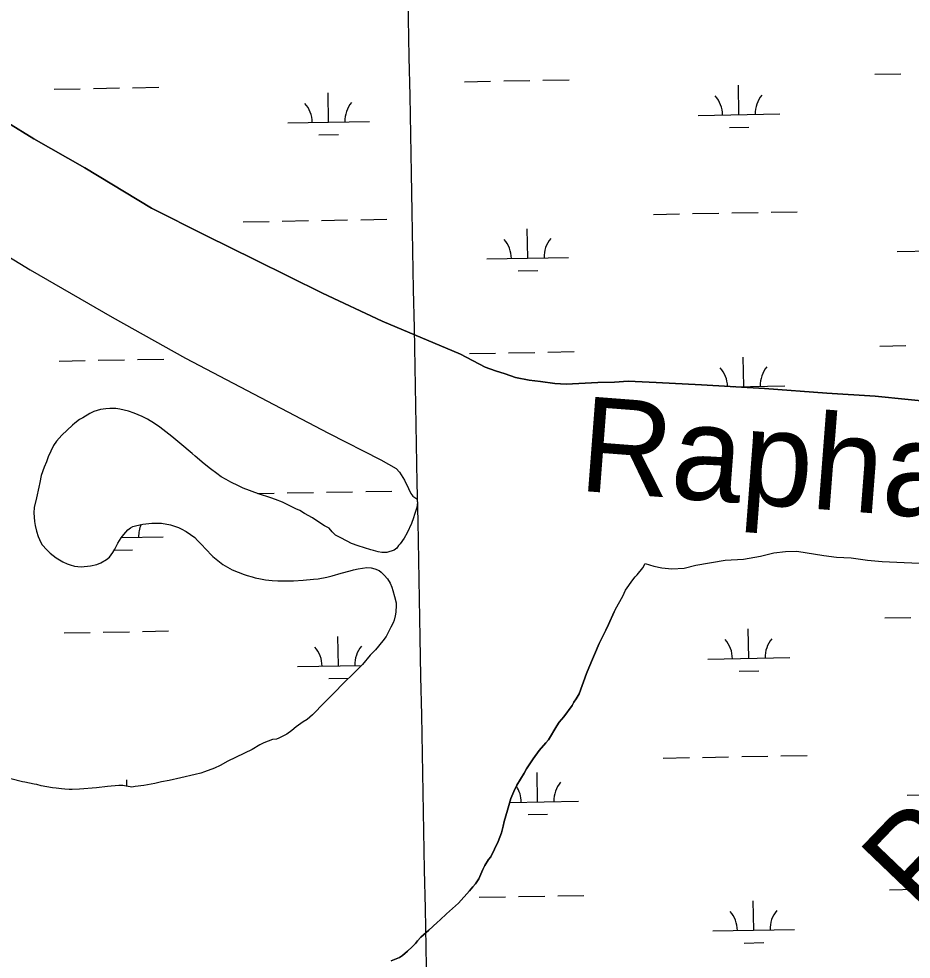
# Model space of a CAD drawing. Extents: x 3957609 to 3995875, y 234277 to 260273.
# Drawn here: x 3971801 to 3972892, y 251198 to 252348 of the extents above; entities that cross this region are included whole.
import ezdxf

# ---------------------------------------------------------------- set-up
doc = ezdxf.new("R2010")
doc.units = 0
for name, color, linetype in [('V-GRID-MAJR', 7, 'Continuous'), ('V-RIVR-IDEN', 7, 'Continuous'), ('V-TOPO-SHOR', 7, 'Continuous'), ('V-WETL-SWMP', 7, 'Continuous')]:
    doc.layers.add(name, color=color, linetype=linetype)

msp = doc.modelspace()

# ---------------------------------------------------------------- linework, layer by layer
at = {"layer": 'V-GRID-MAJR'}
msp.add_spline([(3972513.068, 239900.828), (3972455.83, 242927.648), (3972341.236, 248987.469), (3972226.642, 255047.279), (3972169.287, 258080.274)], degree=3, dxfattribs=at)
at = {"layer": 'V-TOPO-SHOR'}
for points in [[(3971429.884, 252268.018), (3971443.683, 252260.164), (3971459.059, 252249.556), (3971499.661, 252228.746), (3971570.618, 252189.474), (3971649.861, 252141.55), (3971729.498, 252093.629), (3971815.051, 252041.385), (3971915.184, 251983.254), (3972005.064, 251933.379), (3972179.691, 251841.498), (3972243.943, 251808.91), (3972262.471, 251798.308), (3972266.418, 251793.587), (3972272.736, 251784.144), (3972277.477, 251773.912), (3972280.639, 251767.614), (3972283.007, 251764.468), (3972287.74, 251760.932)], [(3971753.003, 252242.246), (3971819.63, 252201.786), (3971881.916, 252166.046), (3971963.525, 252116.946), (3972029.749, 252083.18), (3972090.054, 252053.738), (3972172.437, 252012.909), (3972245.356, 251978.37), (3972341.129, 251937.957), (3972371.48, 251922.25), (3972384.092, 251917.544), (3972395.915, 251914.02), (3972408.524, 251909.706), (3972425.072, 251906.188), (3972438.859, 251904.636), (3972456.587, 251902.301), (3972470.372, 251901.535), (3972508.969, 251903.567), (3972529.449, 251903.995), (3972546.381, 251905.203), (3972580.651, 251903.288), (3972635.795, 251900.622), (3972712.999, 251896.02), (3972789.416, 251890.234), (3972848.5, 251886.785), (3972928.86, 251878.642)], [(3972287.74, 251760.932), (3972288.46, 251756.467), (3972287.756, 251750.569), (3972286.691, 251746.817), (3972284.911, 251741.99), (3972283.846, 251737.879), (3972281.356, 251731.086), (3972275.837, 251719.466), (3972272.273, 251712.849), (3972267.46, 251706.232), (3972265.5, 251703.905), (3972263.36, 251700.686), (3972260.149, 251698.181), (3972251.222, 251695.664), (3972245.147, 251695.656), (3972240.679, 251696.362), (3972234.78, 251697.781), (3972231.743, 251698.67), (3972216.193, 251703.647), (3972207.792, 251706.672), (3972202.426, 251709.162), (3972194.023, 251713.617), (3972188.479, 251716.824), (3972184.365, 251720.926), (3972180.785, 251725.386), (3972174.706, 251728.055), (3972162.902, 251735.897), (3972160.041, 251738.037), (3972150.562, 251743.202), (3972144.662, 251746.766), (3972139.835, 251748.902), (3972128.393, 251754.779), (3972123.386, 251757.094), (3972115.163, 251760.295), (3972109.265, 251762.431), (3972094.07, 251767.407), (3972075.481, 251774.346), (3972069.58, 251776.836), (3972060.463, 251781.467), (3972054.56, 251784.674), (3972048.482, 251788.235), (3972043.114, 251791.979), (3972035.424, 251797.685), (3972027.912, 251803.745), (3972016.82, 251813.197), (3972012.884, 251816.762), (3971997.857, 251829.245), (3971988.375, 251837.447), (3971973.707, 251848.678), (3971967.088, 251853.491), (3971958.505, 251858.48), (3971952.068, 251861.863), (3971942.058, 251866.135), (3971935.264, 251868.447), (3971924.721, 251870.932), (3971919.896, 251871.816), (3971912.392, 251871.804), (3971907.569, 251871.44), (3971900.96, 251870.534), (3971892.926, 251868.021), (3971887.749, 251865.691), (3971879.36, 251860.139), (3971875.256, 251857.988), (3971869.724, 251853.87), (3971866.691, 251851.363), (3971853.848, 251839.196), (3971847.071, 251831.86), (3971843.328, 251826.494), (3971837.098, 251812.549), (3971834.785, 251806.293), (3971832.117, 251799.678), (3971828.56, 251789.847), (3971826.608, 251780.912), (3971825.723, 251775.55), (3971822.706, 251762.504), (3971819.69, 251750.708), (3971819.344, 251744.097), (3971820.253, 251733.38), (3971821.154, 251728.557), (3971822.774, 251721.594), (3971824.748, 251715.165), (3971828.154, 251707.845), (3971829.768, 251704.81), (3971835.316, 251698.568), (3971839.252, 251694.82), (3971846.764, 251689.116), (3971854.813, 251684.127), (3971860.177, 251681.635), (3971863.931, 251680.212), (3971869.292, 251678.79), (3971873.044, 251678.262), (3971877.333, 251677.912), (3971888.584, 251679.179), (3971896.443, 251680.98), (3971901.442, 251682.952), (3971908.225, 251686.892), (3971911.792, 251689.936), (3971916.071, 251695.482), (3971918.565, 251699.594), (3971922.307, 251706.746), (3971926.405, 251713.543)], [(3971926.405, 251713.543), (3971929.434, 251717.655), (3971934.249, 251723.023), (3971937.462, 251725.708), (3971940.673, 251727.142), (3971943.71, 251728.041), (3971952.64, 251730.199), (3971963.891, 251731.289), (3971970.68, 251731.477), (3971975.504, 251731.307), (3971986.763, 251729.181), (3971992.483, 251727.404), (3971996.237, 251725.98), (3971999.811, 251724.379), (3972005.714, 251721.352), (3972016.265, 251713.686), (3972019.665, 251710.119), (3972025.391, 251704.589), (3972029.151, 251700.309), (3972038.455, 251690.677), (3972050.442, 251680.691), (3972062.064, 251674.1), (3972076.722, 251668.585), (3972080.476, 251667.52), (3972086.374, 251665.564), (3972090.306, 251664.497), (3972096.561, 251663.078), (3972102.637, 251662.017), (3972111.034, 251661.137), (3972118.003, 251660.791), (3972122.468, 251660.977), (3972128.901, 251660.987), (3972136.939, 251660.821), (3972148.73, 251661.554), (3972161.591, 251662.648), (3972167.307, 251663.371), (3972177.666, 251665.353), (3972184.451, 251666.973), (3972195.166, 251670.205), (3972206.237, 251672.902), (3972210.165, 251674.16), (3972215.879, 251675.6), (3972226.597, 251677.224), (3972232.134, 251676.875), (3972236.603, 251675.632), (3972241.789, 251673.496), (3972244.293, 251671.356), (3972247.871, 251667.789), (3972251.809, 251663.152), (3972255.033, 251657.975), (3972257.185, 251652.975), (3972258.443, 251648.869), (3972260.597, 251641.728), (3972262.398, 251633.87), (3972262.58, 251630.832), (3972262.058, 251622.614), (3972261.351, 251617.789), (3972260.11, 251612.605), (3972258.685, 251609.21), (3972256.192, 251604.024), (3972250.493, 251592.76), (3972246.392, 251587.214), (3972237.299, 251576.483), (3972230.879, 251569.683), (3972221.427, 251558.591), (3972211.439, 251548.749), (3972207.337, 251544.456), (3972201.451, 251538.908), (3972183.259, 251520.654), (3972177.729, 251514.752), (3972169.169, 251506.341), (3972165.779, 251502.583), (3972160.252, 251496.858), (3972153.649, 251491.308), (3972148.652, 251488.085), (3972140.087, 251482.176), (3972135.092, 251477.88), (3972128.667, 251473.224), (3972119.208, 251468.207), (3972116.172, 251466.951), (3972111.349, 251466.587), (3972100.815, 251462.46), (3972095.996, 251460.13), (3972086.536, 251454.577), (3972056.723, 251440.237), (3972047.263, 251435.042), (3972040.302, 251431.636), (3972027.984, 251426.97), (3972023.519, 251425.535), (3972016.734, 251423.737), (3971999.053, 251419.956), (3971984.767, 251416.36), (3971975.657, 251414.738), (3971970.836, 251413.478), (3971967.264, 251412.937), (3971953.868, 251410.414), (3971943.331, 251408.968), (3971939.401, 251408.248), (3971928.144, 251410.195), (3971923.32, 251410.187), (3971909.388, 251409.272)], [(3972567.111, 251681.821), (3972577.751, 251678.688), (3972587.602, 251676.734), (3972599.814, 251675.573), (3972614.779, 251676.386), (3972628.951, 251679.952), (3972664.783, 251685.917), (3972687.231, 251687.136), (3972708.1, 251691.107), (3972724.24, 251695.072), (3972738.812, 251696.671), (3972752.595, 251697.087), (3972785.688, 251691.627), (3972801.052, 251689.682), (3972818.778, 251688.924), (3972838.869, 251686.198), (3972856.987, 251684.259), (3972920.01, 251681.602)], [(3972530.854, 251626.128), (3972539.58, 251641.865), (3972543.142, 251649.373), (3972551.876, 251662.071), (3972554.727, 251665.648), (3972557.226, 251668.153), (3972564.359, 251676.74), (3972567.111, 251681.821)], [(3972530.854, 251626.128), (3972529.072, 251622.73), (3972522.129, 251607.178), (3972518.746, 251600.561), (3972516.61, 251595.734), (3972510.912, 251583.933), (3972498.098, 251554.258), (3972495.249, 251547.286), (3972486.537, 251522.618), (3972482.793, 251516.538), (3972479.942, 251512.245), (3972477.804, 251508.311), (3972467.466, 251494.54), (3972461.938, 251487.921), (3972458.907, 251483.448), (3972448.751, 251466.46), (3972445.72, 251462.526), (3972437.34, 251453.043), (3972430.031, 251443.205), (3972427.714, 251439.271), (3972421.832, 251430.687), (3972418.984, 251425.502), (3972410.253, 251410.658), (3972406.335, 251402.972), (3972402.956, 251394.391), (3972398.512, 251380.27), (3972394.782, 251366.151), (3972393.541, 251360.609), (3972391.231, 251352.567), (3972387.139, 251342.019), (3972378.417, 251323.069), (3972375.564, 251319.848), (3972371.107, 251312.694), (3972368.615, 251307.689), (3972363.452, 251296.068), (3972359.532, 251289.988), (3972356.501, 251286.588), (3972352.221, 251281.401), (3972338.667, 251266.551), (3972324.219, 251253.306), (3972316.549, 251245.97), (3972312.803, 251242.927), (3972302.454, 251233.443), (3972295.854, 251227.714), (3972292.823, 251224.851), (3972288.721, 251220.378), (3972286.224, 251217.159), (3972282.3, 251212.864), (3972276.592, 251207.496), (3972270.348, 251202.483), (3972266.6, 251199.798), (3972256.602, 251195.851)], [(3971909.388, 251409.272), (3971895.992, 251407.641), (3971875.448, 251405.823), (3971866.339, 251405.628), (3971862.765, 251405.622), (3971857.406, 251405.972), (3971853.295, 251406.322), (3971846.684, 251407.205), (3971842.396, 251407.555), (3971828.279, 251410.033), (3971822.915, 251411.455), (3971819.7, 251411.985), (3971808.442, 251414.467), (3971805.403, 251415), (3971775.021, 251422.633)]]:
    msp.add_lwpolyline(points, dxfattribs=at)
at = {"layer": 'V-WETL-SWMP'}
for p, q in [((3972346.071, 252271.505), (3972378.065, 252272.087)), ((3972394.063, 252272.378), (3972426.058, 252272.96)), ((3972442.055, 252273.251), (3972474.05, 252273.832)), ((3972847.896, 252280.63), (3972879.89, 252281.212)), ((3971844.246, 252262.381), (3971876.24, 252262.962)), ((3971892.238, 252263.253), (3971924.232, 252263.835)), ((3971940.23, 252264.126), (3971972.225, 252264.708)), ((3972681.703, 252231.17), (3972681.049, 252267.164)), ((3972179.878, 252222.046), (3972179.224, 252258.04)), ((3972631.712, 252230.261), (3972731.695, 252232.079)), ((3972129.887, 252221.137), (3972229.87, 252222.955)), ((3972669.986, 252215.524), (3972693.982, 252215.96)), ((3972168.161, 252206.399), (3972192.157, 252206.835)), ((3972625.052, 252110.049), (3972657.047, 252110.631)), ((3972673.044, 252110.922), (3972705.039, 252111.504)), ((3972721.036, 252111.795), (3972753.031, 252112.377)), ((3972075.235, 252100.052), (3972107.23, 252100.634)), ((3972123.227, 252100.925), (3972155.222, 252101.506)), ((3972171.219, 252101.797), (3972203.214, 252102.379)), ((3972219.211, 252102.67), (3972251.206, 252103.252)), ((3972577.06, 252109.177), (3972609.055, 252109.759)), ((3972423.416, 252055.633), (3972422.762, 252091.627)), ((3972875.249, 252063.848), (3972975.233, 252065.666)), ((3972373.424, 252054.724), (3972473.408, 252056.542)), ((3972411.699, 252039.986), (3972435.695, 252040.422)), ((3972352.119, 251938.885), (3972384.113, 251939.467)), ((3972400.111, 251939.758), (3972432.106, 251940.34)), ((3972448.103, 251940.631), (3972480.098, 251941.212)), ((3972853.944, 251948.01), (3972885.939, 251948.592)), ((3971850.294, 251929.76), (3971882.288, 251930.342)), ((3971898.286, 251930.633), (3971930.281, 251931.215)), ((3971946.278, 251931.506), (3971978.273, 251932.088)), ((3972687.752, 251898.55), (3972687.097, 251934.544)), ((3972674.557, 251898.31), (3972737.743, 251899.459)), ((3972093.413, 251767.653), (3972113.278, 251768.014)), ((3972129.275, 251768.305), (3972161.27, 251768.886)), ((3972177.267, 251769.177), (3972209.262, 251769.759)), ((3972225.259, 251770.05), (3972257.254, 251770.632)), ((3971926.645, 251713.87), (3971977.631, 251714.797)), ((3971927.639, 251713.888), (3971927.615, 251715.187)), ((3971917.766, 251698.275), (3971939.918, 251698.678)), ((3972859.992, 251615.39), (3972891.987, 251615.972)), ((3971856.342, 251597.14), (3971888.336, 251597.722)), ((3971904.334, 251598.013), (3971936.329, 251598.595)), ((3971952.326, 251598.886), (3971984.321, 251599.468)), ((3972191.975, 251556.806), (3972191.32, 251592.8)), ((3972693.8, 251565.93), (3972693.145, 251601.924)), ((3972643.808, 251565.021), (3972743.791, 251566.839)), ((3972141.983, 251555.897), (3972220.136, 251557.318)), ((3972682.082, 251550.284), (3972706.078, 251550.72)), ((3972180.257, 251541.159), (3972204.253, 251541.595)), ((3972589.156, 251443.937), (3972621.151, 251444.519)), ((3972637.148, 251444.809), (3972669.143, 251445.391)), ((3972685.14, 251445.682), (3972717.135, 251446.264)), ((3972733.132, 251446.555), (3972765.127, 251447.136)), ((3972435.512, 251390.393), (3972434.858, 251426.387)), ((3971933.177, 251409.325), (3971933.033, 251417.262)), ((3972887.346, 251398.608), (3972987.329, 251400.426)), ((3972401.502, 251389.774), (3972485.504, 251391.302)), ((3972423.795, 251374.746), (3972447.791, 251375.182)), ((3972866.04, 251282.77), (3972898.035, 251283.352)), ((3972364.215, 251273.645), (3972396.21, 251274.227)), ((3972412.207, 251274.518), (3972444.202, 251275.1)), ((3972460.199, 251275.39), (3972492.194, 251275.972)), ((3972699.848, 251233.31), (3972699.193, 251269.304)), ((3972649.856, 251232.401), (3972749.839, 251234.219)), ((3972688.13, 251217.664), (3972712.126, 251218.1))]:
    msp.add_line(p, q, dxfattribs=at)
for points in [[(3972928.86, 251878.643), (3972848.5, 251886.785), (3972789.416, 251890.234), (3972712.998, 251896.019), (3972635.795, 251900.621), (3972580.65, 251903.289), (3972546.382, 251905.203), (3972529.448, 251903.994), (3972508.968, 251903.567), (3972470.373, 251901.535), (3972456.587, 251902.301), (3972438.859, 251904.635), (3972425.072, 251906.189), (3972408.524, 251909.707), (3972395.914, 251914.019), (3972384.092, 251917.544), (3972371.481, 251922.25), (3972341.129, 251937.956), (3972245.357, 251978.369), (3972172.437, 252012.91), (3972090.055, 252053.739), (3972029.748, 252083.181), (3971963.525, 252116.946), (3971881.917, 252166.046), (3971819.63, 252201.787), (3971753.003, 252242.247)], [(3971729.498, 252093.629), (3971815.05, 252041.384), (3971915.184, 251983.254), (3972005.064, 251933.379), (3972179.692, 251841.497), (3972243.943, 251808.911), (3972262.472, 251798.307), (3972266.418, 251793.587), (3972272.735, 251784.144), (3972277.478, 251773.911), (3972280.639, 251767.615), (3972283.007, 251764.468), (3972287.739, 251760.931), (3972288.461, 251756.466), (3972287.756, 251750.569), (3972286.69, 251746.816), (3972284.911, 251741.989), (3972283.846, 251737.879), (3972281.356, 251731.086), (3972275.836, 251719.465), (3972272.274, 251712.849), (3972267.461, 251706.231), (3972265.5, 251703.905), (3972263.361, 251700.686), (3972260.149, 251698.18), (3972251.221, 251695.664), (3972245.147, 251695.655), (3972240.679, 251696.362), (3972234.781, 251697.782), (3972231.743, 251698.67), (3972216.192, 251703.647), (3972207.791, 251706.671), (3972202.427, 251709.163), (3972194.023, 251713.616), (3972188.48, 251716.823), (3972184.364, 251720.925), (3972180.784, 251725.386), (3972174.706, 251728.056), (3972162.902, 251735.897), (3972160.04, 251738.036), (3972150.563, 251743.202), (3972144.662, 251746.765), (3972139.835, 251748.902), (3972128.392, 251754.779), (3972123.386, 251757.093), (3972115.163, 251760.295), (3972109.264, 251762.43), (3972094.071, 251767.407), (3972075.48, 251774.345), (3972069.58, 251776.836), (3972060.462, 251781.467), (3972054.561, 251784.673), (3972048.481, 251788.236), (3972043.115, 251791.979), (3972035.424, 251797.684), (3972027.911, 251803.746), (3972016.82, 251813.196), (3972012.883, 251816.763), (3971997.857, 251829.244), (3971988.375, 251837.447), (3971973.707, 251848.678), (3971967.089, 251853.491), (3971958.506, 251858.48), (3971952.069, 251861.864), (3971942.058, 251866.135), (3971935.265, 251868.447), (3971924.721, 251870.931), (3971919.896, 251871.816), (3971912.393, 251871.804), (3971907.57, 251871.439), (3971900.961, 251870.535), (3971892.926, 251868.021), (3971887.749, 251865.69), (3971879.361, 251860.139), (3971875.256, 251857.988), (3971869.724, 251853.87), (3971866.691, 251851.364), (3971853.848, 251839.195), (3971847.071, 251831.86), (3971843.328, 251826.494), (3971837.097, 251812.549), (3971834.785, 251806.293), (3971832.116, 251799.678), (3971828.559, 251789.847), (3971826.608, 251780.911), (3971825.723, 251775.55), (3971822.707, 251762.504), (3971819.689, 251750.708), (3971819.343, 251744.097), (3971820.253, 251733.379), (3971821.154, 251728.557), (3971822.773, 251721.593), (3971824.749, 251715.164), (3971828.155, 251707.845), (3971829.768, 251704.811)], [(3971829.768, 251704.811), (3971835.316, 251698.567), (3971839.252, 251694.821), (3971846.765, 251689.117), (3971854.812, 251684.127), (3971860.176, 251681.635), (3971863.93, 251680.212), (3971869.292, 251678.791), (3971873.044, 251678.261), (3971877.332, 251677.911), (3971888.585, 251679.18), (3971896.443, 251680.979), (3971901.442, 251682.952), (3971908.225, 251686.893), (3971911.793, 251689.936), (3971916.071, 251695.481), (3971918.566, 251699.594), (3971922.306, 251706.746), (3971926.404, 251713.542), (3971929.434, 251717.656), (3971934.249, 251723.023), (3971937.461, 251725.708), (3971940.674, 251727.142), (3971943.71, 251728.04), (3971952.639, 251730.199), (3971963.892, 251731.289), (3971970.681, 251731.478), (3971975.504, 251731.307), (3971986.763, 251729.182), (3971992.483, 251727.404), (3971996.237, 251725.981), (3971999.812, 251724.379), (3972005.713, 251721.352), (3972016.265, 251713.687), (3972019.665, 251710.119), (3972025.391, 251704.59), (3972029.15, 251700.309), (3972038.455, 251690.676), (3972050.441, 251680.691), (3972062.064, 251674.1), (3972076.722, 251668.585), (3972080.476, 251667.52), (3972086.374, 251665.564), (3972090.306, 251664.498), (3972096.561, 251663.079), (3972102.637, 251662.017), (3972111.035, 251661.137), (3972118.003, 251660.791), (3972122.469, 251660.977), (3972128.901, 251660.988), (3972136.94, 251660.822), (3972148.73, 251661.555), (3972161.591, 251662.648), (3972167.307, 251663.372), (3972177.665, 251665.354), (3972184.451, 251666.973), (3972195.165, 251670.206), (3972206.237, 251672.903), (3972210.166, 251674.16), (3972215.88, 251675.599), (3972226.597, 251677.224), (3972232.135, 251676.875), (3972236.604, 251675.632), (3972241.788, 251673.496), (3972244.293, 251671.357), (3972247.871, 251667.789), (3972251.809, 251663.151), (3972255.033, 251657.975), (3972257.185, 251652.976), (3972258.442, 251648.869), (3972260.598, 251641.727), (3972262.397, 251633.869), (3972262.58, 251630.832), (3972262.058, 251622.614), (3972261.351, 251617.789), (3972260.109, 251612.606), (3972258.685, 251609.209), (3972256.192, 251604.024), (3972250.493, 251592.76), (3972246.393, 251587.215), (3972237.299, 251576.482), (3972230.879, 251569.683), (3972221.428, 251558.591), (3972211.44, 251548.749), (3972207.338, 251544.455), (3972201.451, 251538.907), (3972183.258, 251520.655), (3972177.73, 251514.751), (3972169.168, 251506.34), (3972165.78, 251502.583), (3972160.251, 251496.858), (3972153.649, 251491.309), (3972148.652, 251488.085), (3972140.087, 251482.176), (3972135.091, 251477.88), (3972128.667, 251473.225), (3972119.207, 251468.207), (3972116.172, 251466.952), (3972111.349, 251466.587), (3972100.815, 251462.461), (3972095.995, 251460.13)], [(3972599.813, 251675.573), (3972614.778, 251676.385), (3972628.951, 251679.952), (3972664.783, 251685.918), (3972687.231, 251687.136), (3972708.099, 251691.108), (3972724.241, 251695.072), (3972738.811, 251696.671), (3972752.595, 251697.087), (3972785.688, 251691.627), (3972801.052, 251689.682), (3972818.777, 251688.923), (3972838.868, 251686.198), (3972856.988, 251684.258), (3972920.01, 251681.603)], [(3972256.602, 251195.851), (3972266.6, 251199.798), (3972270.348, 251202.483), (3972276.593, 251207.496), (3972282.301, 251212.864), (3972286.224, 251217.158), (3972288.72, 251220.378), (3972292.822, 251224.851), (3972295.854, 251227.714), (3972302.455, 251233.442), (3972312.802, 251242.927), (3972316.548, 251245.97), (3972324.219, 251253.307), (3972338.668, 251266.551), (3972352.221, 251281.401), (3972356.501, 251286.588), (3972359.532, 251289.988), (3972363.453, 251296.068), (3972368.615, 251307.689), (3972371.108, 251312.695), (3972375.563, 251319.848), (3972378.416, 251323.069), (3972387.139, 251342.02), (3972391.231, 251352.567), (3972393.541, 251360.61), (3972394.782, 251366.15), (3972398.511, 251380.269), (3972402.955, 251394.39), (3972406.335, 251402.971), (3972410.253, 251410.659), (3972418.983, 251425.501), (3972421.833, 251430.687), (3972427.715, 251439.271), (3972430.031, 251443.205), (3972437.34, 251453.043), (3972445.721, 251462.525), (3972448.752, 251466.46), (3972458.908, 251483.448), (3972461.938, 251487.92), (3972467.465, 251494.539), (3972477.805, 251508.311), (3972479.942, 251512.245), (3972482.794, 251516.537), (3972486.536, 251522.618), (3972495.25, 251547.286), (3972498.097, 251554.258), (3972510.912, 251583.934), (3972516.61, 251595.734), (3972518.746, 251600.561), (3972522.129, 251607.177), (3972529.072, 251622.731), (3972530.853, 251626.128), (3972539.581, 251641.864), (3972543.142, 251649.373), (3972551.876, 251662.071), (3972554.728, 251665.649), (3972557.225, 251668.154), (3972564.358, 251676.74), (3972567.112, 251681.822), (3972577.751, 251678.688), (3972587.601, 251676.735), (3972599.813, 251675.573)], [(3972095.995, 251460.13), (3972086.536, 251454.577), (3972056.724, 251440.237), (3972047.264, 251435.041), (3972040.302, 251431.635), (3972027.983, 251426.97), (3972023.519, 251425.534), (3972016.733, 251423.736), (3971999.053, 251419.956), (3971984.766, 251416.36), (3971975.658, 251414.738), (3971970.836, 251413.479), (3971967.264, 251412.938), (3971953.869, 251410.415), (3971943.331, 251408.969), (3971939.402, 251408.248), (3971928.144, 251410.195), (3971923.32, 251410.187), (3971909.387, 251409.271), (3971895.991, 251407.642), (3971875.449, 251405.822), (3971866.338, 251405.629), (3971862.765, 251405.623), (3971857.405, 251405.972), (3971853.295, 251406.322), (3971846.684, 251407.205), (3971842.395, 251407.555), (3971828.278, 251410.034), (3971822.916, 251411.454), (3971819.7, 251411.985), (3971808.441, 251414.468), (3971805.403, 251414.999), (3971775.02, 251422.632)]]:
    msp.add_lwpolyline(points, dxfattribs=at)
for centre, start, end in [((3972626.461, 252230.641), 0.269879, 41.813537), ((3972736.929, 252232.649), 140.269876, 181.813534), ((3972124.636, 252221.516), 0.269879, 41.813537), ((3972235.104, 252223.525), 140.269876, 181.813534), ((3972368.174, 252055.103), 0.269879, 41.813537), ((3972478.641, 252057.112), 140.269876, 181.813534), ((3972632.509, 251898.021), 1.130652, 41.813537), ((3972742.977, 251900.029), 140.269876, 181.813534), ((3971982.864, 251715.367), 155.962557, 181.813534), ((3972638.557, 251565.401), 0.269879, 41.813537), ((3972749.025, 251567.409), 140.269876, 181.813534), ((3972136.732, 251556.276), 0.269879, 41.813537), ((3972247.2, 251558.285), 140.269876, 181.813534), ((3972380.27, 251389.863), 0.269879, 33.653236), ((3972490.737, 251391.872), 140.269876, 181.813534), ((3972644.605, 251232.781), 0.269879, 41.813537), ((3972755.073, 251234.789), 140.269876, 181.813534)]:
    msp.add_arc(centre, 35.246, start, end, dxfattribs=at)

# ---------------------------------------------------------------- texts
at = {"layer": 'V-RIVR-IDEN'}
for s, rotation, p in [('Raphael', 355.607086, (3972484.561, 251771.179)), ('Pass', 46.21889, (3972906.75, 251246.137))]:
    msp.add_text(s, height=115.9998, rotation=rotation, dxfattribs=at).set_placement(p)

doc.saveas('drawing.dxf')
